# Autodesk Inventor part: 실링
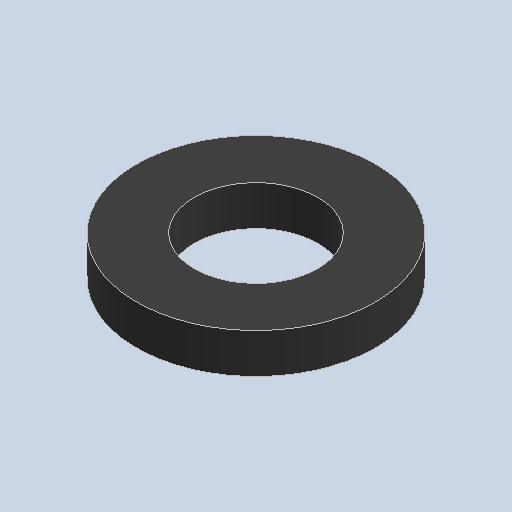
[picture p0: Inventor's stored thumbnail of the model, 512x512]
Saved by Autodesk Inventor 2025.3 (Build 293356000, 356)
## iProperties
Created: 2025-10
Part Number: 실링
Material: 고무
Document SubType Name: Modeling
Designer: USER
Density: 0.93 g/cm^3
Appearance: 기본값
Author: jhkim
Sending System: Autodesk Inventor 2026
Preprocessor: ST-DEVELOPER v20.1
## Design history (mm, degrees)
feature "솔리드1"
node "솔리드2"
